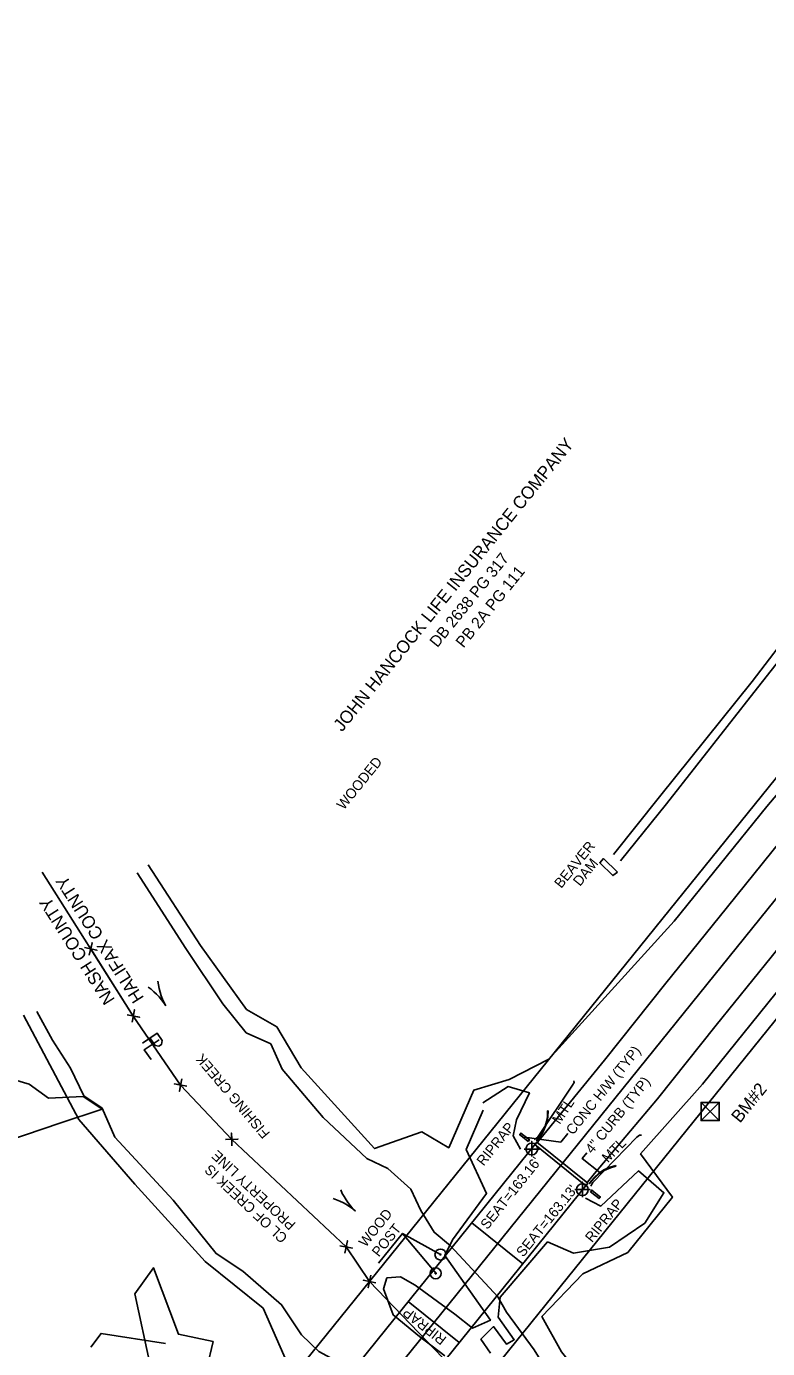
# Model space of a CAD drawing. Extents: x 2292498 to 2294521, y 891760 to 894087.
# Drawn here: x 2293733 to 2294026, y 893552 to 894075 of the extents above; entities that cross this region are included whole.
import ezdxf

# ---------------------------------------------------------------- set-up
doc = ezdxf.new("R2010")
doc.units = 0
for name, color, linetype in [('CTL Vertical Benchmark CELL', 7, 'Continuous'), ('CTL Vertical Benchmark Text', 7, 'Continuous'), ('Exist Boundary County Line', 7, 'Continuous'), ('Exist Boundary County Line Text', 7, 'Continuous'), ('Exist Environmental Wetland Boundary', 7, 'Continuous'), ('Exist Environmental Wetland Boundary Leader', 7, 'Continuous'), ('Exist Guardrail', 7, 'Continuous'), ('Exist Guardrail Text', 7, 'Continuous'), ('Exist Horizontal Alignment', 7, 'Continuous'), ('Exist Hydro Jurisdictional Stream or Body of Water', 7, 'Continuous'), ('Exist Hydro Jurisdictional Stream or Body of Water Text', 7, 'Continuous'), ('Exist Hydro Stream Flow Arrow CELL', 7, 'Continuous'), ('Exist Hydro Stream or Body of Water', 7, 'Continuous'), ('Exist Other Culture Area Outline', 7, 'Continuous'), ('Exist Other Culture Area Outline Text', 7, 'Continuous'), ('Exist Other Culture Located Object CELL', 7, 'Continuous'), ('Exist Other Culture Located Object Leader', 7, 'Continuous'), ('Exist Other Culture Located Object Text', 7, 'Continuous'), ('Exist Property Corner CELL', 7, 'Continuous'), ('Exist Property Deed Book Text', 7, 'Continuous'), ('Exist Property Line', 7, 'Continuous'), ('Exist Property Line Text', 7, 'Continuous'), ('Exist Property Owner Text', 7, 'Continuous'), ('Exist Property PL Symbol CELL', 7, 'Continuous'), ('Exist Right of Way Line', 7, 'Continuous'), ('Exist Roads Curbs', 7, 'Continuous'), ('Exist Roads Curbs Leader', 7, 'Continuous'), ('Exist Roads Curbs Text', 7, 'Continuous'), ('Exist Roads EOP', 7, 'Continuous'), ('Exist Structure Major Bridge Seam', 7, 'Continuous'), ('Exist Structure Major Bridge Seat Cogo Point CELL', 7, 'Continuous'), ('Exist Structure Major Bridge Seat Top Elevation', 7, 'Continuous'), ('Exist Structure Major Bridge WW', 7, 'Continuous'), ('Exist Structure Major Bridge WW Leader', 7, 'Continuous'), ('Exist Structure Major Bridge WW Text', 7, 'Continuous'), ('Exist Structure Major Deck Tunnel Box Culvert', 7, 'Continuous'), ('Exist Vegetation Woods Line', 7, 'Continuous'), ('Exist Vegetation Woods Line Text', 7, 'Continuous')]:
    doc.layers.add(name, color=color, linetype=linetype)

msp = doc.modelspace()

# ---------------------------------------------------------------- linework, layer by layer
at = {"layer": 'CTL Vertical Benchmark CELL'}
msp.add_line((2294003.6, 893645.94), (2294003.6, 893645.94), dxfattribs=at)
msp.add_lwpolyline([(2294000, 893649.53), (2294007.18, 893649.53), (2294007.18, 893642.34), (2294000, 893642.34)], close=True, dxfattribs=at)
for points in [[(2294007.18, 893649.53), (2294000, 893642.34), (2294003.59, 893645.93), (2294007.18, 893642.34), (2294000, 893649.53)], [(2294003.59, 893645.93), (2294007.18, 893649.53), (2294000, 893649.53), (2294003.59, 893645.93)], [(2294003.59, 893645.93), (2294000, 893642.34), (2294007.18, 893642.34), (2294003.59, 893645.93)]]:
    msp.add_lwpolyline(points, dxfattribs=at)
at = {"layer": 'Exist Boundary County Line'}
msp.add_lwpolyline([(2294085.79, 893359.86), (2293944.67, 893485.57), (2293917.22, 893516.72), (2293910.74, 893535.04), (2293868.86, 893578.67), (2293859.65, 893592.34), (2293814.35, 893634.9), (2293794.17, 893656.4), (2293775.45, 893683.7), (2293739.35, 893740.54)], dxfattribs=at)
at = {"layer": 'Exist Environmental Wetland Boundary'}
for points in [[(2293763.13, 893646.9), (2293755.65, 893651.85), (2293741.86, 893651.22), (2293734.32, 893656.8), (2293714.14, 893662.61)], [(2293710.75, 893557.16), (2293717.8, 893589.35), (2293701.17, 893615.08), (2293712.47, 893629.8), (2293746.4, 893641.37), (2293763.13, 893646.9)]]:
    msp.add_lwpolyline(points, dxfattribs=at)
msp.add_lwpolyline([(2293806.99, 893554.95), (2293804.55, 893544.37), (2293782.24, 893545.05), (2293776.11, 893573.81), (2293783.44, 893584.11), (2293793.31, 893557.79)], close=True, dxfattribs=at)
at = {"layer": 'Exist Environmental Wetland Boundary Leader'}
msp.add_lwpolyline([(2293788.18, 893554.1), (2293762.68, 893558.12), (2293758.65, 893552.66)], dxfattribs=at)
at = {"layer": 'Exist Guardrail'}
for points in [[(2293934.04, 893634.81), (2293935.26, 893635.64), (2293949.18, 893656.3), (2293949.85, 893657.35), (2293949.68, 893658.04)], [(2293976.47, 893636.59), (2293975.69, 893636.57), (2293974.64, 893635.71), (2293957.21, 893617.78), (2293956.77, 893617.11), (2293956.36, 893616.38)]]:
    msp.add_lwpolyline(points, dxfattribs=at)
at = {"layer": 'Exist Horizontal Alignment'}
msp.add_line((2293668.45, 893282.57), (2294292.7, 894056.1), dxfattribs=at)
at = {"layer": 'Exist Hydro Jurisdictional Stream or Body of Water'}
for points in [[(2293876.14, 893623.32), (2293867.85, 893627.29), (2293850.52, 893643.52), (2293834.35, 893662.67), (2293829.82, 893672.66), (2293820.14, 893677.06), (2293810.8, 893688.53), (2293796.25, 893710.39), (2293777.03, 893740.29)], [(2293763.14, 893647.29), (2293755.83, 893652.18), (2293750.6, 893663.12), (2293743.5, 893674.18), (2293737.3, 893685.5)], [(2293841.91, 893557.56), (2293834.07, 893569.44), (2293818.72, 893582.82), (2293808.2, 893589.71), (2293791.2, 893610.86), (2293768.19, 893635.74), (2293763.14, 893647.29)], [(2293972.26, 893510.52), (2293957.43, 893525.98), (2293944.05, 893535.44), (2293934.04, 893551.57), (2293923.07, 893566.54), (2293919.68, 893572.56), (2293900.86, 893592.82), (2293894.49, 893598.15), (2293889.13, 893606.73), (2293885.23, 893615.23), (2293876.14, 893623.32)], [(2293922.02, 893454.77), (2293917.08, 893460.63), (2293906.04, 893474.31), (2293901.31, 893485.66), (2293890.38, 893498), (2293885.17, 893503.23), (2293885.42, 893510.43), (2293887.93, 893517.16), (2293886.05, 893521.05), (2293873.12, 893534.01), (2293866.59, 893539.82), (2293859.83, 893545.01), (2293848.78, 893550.96), (2293841.91, 893557.56)]]:
    msp.add_lwpolyline(points, dxfattribs=at)
at = {"layer": 'Exist Hydro Stream Flow Arrow CELL'}
for p, q in [((2293785.78, 893692), (2293785.78, 893692)), ((2293859.67, 893609.82), (2293859.67, 893609.82))]:
    msp.add_line(p, q, dxfattribs=at)
for points in [[(2293781.27, 893695.15), (2293782.46, 893694.3), (2293783.59, 893693.31), (2293784.68, 893692.31), (2293785.67, 893691.26), (2293786.61, 893690.12), (2293787.51, 893688.92), (2293788.32, 893687.7)], [(2293785.21, 893697.47), (2293785.37, 893696.01), (2293785.7, 893694.55), (2293786.04, 893693.11), (2293786.48, 893691.74), (2293787.02, 893690.36), (2293787.64, 893688.99), (2293788.32, 893687.7)], [(2293857.53, 893614.88), (2293858.11, 893613.53), (2293858.85, 893612.23), (2293859.6, 893610.95), (2293860.43, 893609.77), (2293861.35, 893608.61), (2293862.33, 893607.48), (2293863.36, 893606.44)], [(2293854.44, 893611.5), (2293855.83, 893611.04), (2293857.19, 893610.42), (2293858.53, 893609.79), (2293859.79, 893609.07), (2293861.02, 893608.26), (2293862.23, 893607.37), (2293863.36, 893606.44)]]:
    msp.add_lwpolyline(points, dxfattribs=at)
at = {"layer": 'Exist Hydro Stream or Body of Water'}
for points in [[(2293965.42, 893747.6), (2293983.52, 893770.46), (2294020.17, 893816.01), (2294037.74, 893838.96), (2294073.63, 893884.39), (2294095.2, 893911.15), (2294125.99, 893949.6), (2294148.73, 893977.27), (2294148.61, 893978.43), (2294147.33, 893979.83), (2294128.27, 893998.23), (2294100.51, 894022.9)], [(2293968.14, 893745.05), (2293986.28, 893767.63), (2294022.34, 893813.58), (2294040.46, 893836.56), (2294069.7, 893872.94), (2294098.71, 893908.94), (2294129.49, 893948.14), (2294150.33, 893973.58), (2294152.51, 893976.22), (2294152.08, 893979.35), (2294149.75, 893982.98), (2294131.07, 893999.21), (2294104.21, 894024.33)]]:
    msp.add_lwpolyline(points, dxfattribs=at)
at = {"layer": 'Exist Other Culture Area Outline'}
for points in [[(2293966.96, 893740.61), (2293961.48, 893746.01), (2293959.94, 893744.35), (2293965.14, 893739.26), (2293966.96, 893740.61)], [(2293913.73, 893649.35), (2293923.67, 893655.79), (2293932.11, 893653.29), (2293926.96, 893642.65), (2293925.73, 893636.34), (2293928.53, 893631.02)], [(2293898.65, 893549.29), (2293888.68, 893556.92), (2293878.25, 893565.42), (2293874.45, 893575.74), (2293875.73, 893580.06), (2293881.14, 893580.52), (2293886.91, 893577.23), (2293902.55, 893565.71), (2293909.58, 893560.24), (2293916.7, 893563.37), (2293898.6, 893588.98), (2293901.73, 893595.13), (2293915.17, 893613.5), (2293907.14, 893630.86), (2293913.77, 893646.48)], [(2293954.36, 893611.57), (2293960.42, 893608.48), (2293975.24, 893622.43), (2293985.31, 893613.8), (2293977.71, 893601.77), (2293963.83, 893592.29), (2293949.53, 893589.84), (2293939.27, 893594.36), (2293920.58, 893572.42), (2293919.78, 893564.62), (2293926.1, 893555.62), (2293923.01, 893553.94), (2293917.96, 893560.82), (2293912.96, 893555.9), (2293916.74, 893550.26)]]:
    msp.add_lwpolyline(points, dxfattribs=at)
at = {"layer": 'Exist Other Culture Located Object CELL'}
for centre, radius in [((2293896.94, 893589.33), 2.18), ((2293896.94, 893589.33), 0.24), ((2293895.05, 893581.92), 2.18), ((2293895.05, 893581.92), 0.24)]:
    msp.add_circle(centre, radius, dxfattribs=at)
at = {"layer": 'Exist Other Culture Located Object Leader'}
msp.add_line((2293896.94, 893589.33), (2293881.94, 893597.66), dxfattribs=at)
msp.add_lwpolyline([(2293895.24, 893581.77), (2293881.94, 893597.66), (2293872.48, 893585.97)], dxfattribs=at)
at = {"layer": 'Exist Property Corner CELL'}
for p, q in [((2293758.6, 893710.24), (2293758.6, 893710.24)), ((2293775.45, 893683.7), (2293775.45, 893683.7)), ((2293794.17, 893656.4), (2293794.17, 893656.4)), ((2293814.35, 893634.9), (2293814.35, 893634.9)), ((2293859.65, 893592.34), (2293859.65, 893592.34)), ((2293868.86, 893578.67), (2293868.86, 893578.67))]:
    msp.add_line(p, q, dxfattribs=at)
for points in [[(2293756.16, 893710.78), (2293761.04, 893709.69), (2293758.6, 893710.24), (2293759.14, 893712.68), (2293758.05, 893707.8)], [(2293773, 893684.16), (2293777.91, 893683.24), (2293775.45, 893683.7), (2293775.91, 893686.16), (2293774.99, 893681.25)], [(2293796.63, 893655.94), (2293791.71, 893656.86), (2293794.17, 893656.4), (2293793.71, 893653.94), (2293794.63, 893658.86)], [(2293811.85, 893634.82), (2293816.84, 893634.98), (2293814.35, 893634.9), (2293814.27, 893637.4), (2293814.42, 893632.4)], [(2293857.19, 893592.81), (2293862.1, 893591.86), (2293859.65, 893592.34), (2293860.12, 893594.79), (2293859.17, 893589.88)], [(2293871.31, 893578.2), (2293866.4, 893579.15), (2293868.86, 893578.67), (2293868.38, 893576.22), (2293869.33, 893581.13)]]:
    msp.add_lwpolyline(points, dxfattribs=at)
at = {"layer": 'Exist Property Line'}
for p, q in [((2293775.45, 893683.7), (2293758.6, 893710.24)), ((2293859.65, 893592.34), (2293814.35, 893634.9))]:
    msp.add_line(p, q, dxfattribs=at)
for points in [[(2293794.17, 893656.4), (2293775.45, 893683.7)], [(2293814.35, 893634.9), (2293794.17, 893656.4)], [(2293868.86, 893578.67), (2293859.65, 893592.34)]]:
    msp.add_lwpolyline(points, dxfattribs=at)
at = {"layer": 'Exist Property PL Symbol CELL'}
msp.add_line((2293782.43, 893673.52), (2293782.43, 893673.52), dxfattribs=at)
for points in [[(2293779.06, 893672.97), (2293784.86, 893676.95), (2293786.87, 893674.01), (2293786.56, 893672.38), (2293785.6, 893671.73), (2293784.04, 893672.06), (2293782.02, 893675)], [(2293785.61, 893674.32), (2293779.78, 893670.32), (2293782.45, 893666.43)]]:
    msp.add_lwpolyline(points, dxfattribs=at)
at = {"layer": 'Exist Right of Way Line'}
for p, q in [((2293645.1, 893301.41), (2294269.35, 894074.94)), ((2293691.79, 893263.73), (2294316.04, 894037.26))]:
    msp.add_line(p, q, dxfattribs=at)
at = {"layer": 'Exist Roads Curbs'}
for points in [[(2293939.29, 893646.19), (2293939.21, 893643.84), (2293938.91, 893641.94), (2293938.33, 893640.17), (2293937.23, 893637.76), (2293936.2, 893636.2), (2293934.87, 893634.4)], [(2293939.48, 893646.14), (2293939.4, 893643.82), (2293939.1, 893641.89), (2293938.5, 893640.1), (2293937.39, 893637.67), (2293936.35, 893636.09), (2293935.02, 893634.29), (2293934.87, 893634.4)], [(2293939.29, 893646.19), (2293939.48, 893646.14)], [(2293966.28, 893624.56), (2293964.02, 893623.84), (2293961.55, 893622.86), (2293959.58, 893621.55), (2293957.67, 893619.76), (2293955.71, 893617.52)], [(2293966.31, 893624.27), (2293964.12, 893623.57), (2293961.68, 893622.61), (2293959.75, 893621.33), (2293957.87, 893619.56), (2293955.92, 893617.33), (2293955.71, 893617.52)], [(2293966.31, 893624.27), (2293966.28, 893624.56)]]:
    msp.add_lwpolyline(points, dxfattribs=at)
at = {"layer": 'Exist Roads Curbs Leader'}
msp.add_lwpolyline([(2293960.02, 893621.85), (2293953.01, 893627.3), (2293954.84, 893629.56)], dxfattribs=at)
at = {"layer": 'Exist Roads EOP'}
for points in [[(2293935.28, 893633.81), (2293937.79, 893636.87), (2293961.83, 893666.23), (2293986.02, 893696.74), (2294007.23, 893722.82), (2294031.33, 893752.69), (2294058.41, 893786.02), (2294082.69, 893816.27), (2294107.66, 893847.21), (2294131.39, 893876.6), (2294158.26, 893909.62), (2294184.25, 893942.29), (2294211.73, 893976.1), (2294235.74, 894006.24), (2294255.79, 894031.21), (2294282.38, 894064.31)], [(2293955.11, 893617.9), (2293957.85, 893621.39), (2293982.73, 893650.99), (2294005.99, 893680.08), (2294027.69, 893706.97), (2294051.48, 893736.65), (2294078.15, 893769.54), (2294102.63, 893799.93), (2294128.01, 893831.31), (2294151.11, 893860.1), (2294178.02, 893893.21), (2294203.53, 893924.91), (2294231.5, 893959.53), (2294255.32, 893989.22), (2294275.52, 894013.95), (2294303.02, 894047.9)]]:
    msp.add_lwpolyline(points, dxfattribs=at)
at = {"layer": 'Exist Structure Major Bridge Seam'}
for p, q in [((2293934.29, 893632.85), (2293954.37, 893616.51)), ((2293909.32, 893601.88), (2293929.46, 893585.6)), ((2293884.2, 893570.82), (2293904.37, 893554.48))]:
    msp.add_line(p, q, dxfattribs=at)
at = {"layer": 'Exist Structure Major Bridge Seat Cogo Point CELL'}
for points in [[(2293930.06, 893631.08), (2293936.06, 893631.08), (2293933.06, 893631.08), (2293933.06, 893634.08), (2293933.06, 893628.08)], [(2293950.07, 893615), (2293956.07, 893615), (2293953.07, 893615), (2293953.07, 893618), (2293953.07, 893612)]]:
    msp.add_lwpolyline(points, dxfattribs=at)
for centre in [(2293933.06, 893631.08), (2293953.07, 893615)]:
    msp.add_circle(centre, 2.34, dxfattribs=at)
at = {"layer": 'Exist Structure Major Bridge WW'}
for points in [[(2293931.59, 893634.11), (2293929.35, 893635.89), (2293928.23, 893636.79), (2293928.71, 893637.41), (2293929.89, 893636.49), (2293932.1, 893634.73), (2293931.59, 893634.11)], [(2293956.28, 893614.2), (2293958.55, 893612.43), (2293959.64, 893611.48), (2293960.18, 893612.07), (2293959.04, 893613.02), (2293956.78, 893614.82), (2293956.28, 893614.2)]]:
    msp.add_lwpolyline(points, dxfattribs=at)
at = {"layer": 'Exist Structure Major Bridge WW Leader'}
msp.add_lwpolyline([(2293930.13, 893635.71), (2293944.53, 893633.79), (2293947.35, 893637.28)], dxfattribs=at)
at = {"layer": 'Exist Structure Major Deck Tunnel Box Culvert'}
msp.add_lwpolyline([(2293955.25, 893617.63), (2293935.05, 893633.81), (2293808.22, 893476.45), (2293828.45, 893460.21), (2293955.25, 893617.63)], dxfattribs=at)
at = {"layer": 'Exist Vegetation Woods Line'}
for points in [[(2294275.43, 894075.18), (2294226.51, 894014.61), (2294183.35, 893961.16), (2294158.03, 893929.81), (2294068.65, 893816.83), (2294026.01, 893766.63), (2293989.31, 893721.19), (2293939.84, 893666.63), (2293924.14, 893658.56), (2293910.07, 893654.4), (2293900.21, 893631.61), (2293889.51, 893637.85), (2293870.86, 893631.28), (2293841.9, 893663.23), (2293832.19, 893679.37), (2293820.24, 893686.32), (2293801.97, 893711.56), (2293781.32, 893743.5)], [(2294054.09, 893434.89), (2294014.85, 893475.1), (2293994.42, 893496.91), (2293989.72, 893508.14), (2293970.8, 893518.83), (2293959.99, 893531.71), (2293944.74, 893550.81), (2293937.07, 893564.86), (2293953.29, 893581.7), (2293971.02, 893590.11), (2293988.69, 893612), (2293976.08, 893629.18), (2294000.58, 893656.8), (2294032.96, 893696.89), (2294066.89, 893733.51), (2294113.65, 893791.41), (2294145.47, 893830.82), (2294186.13, 893872.69), (2294234.1, 893935.06), (2294280.63, 893992.69), (2294320.98, 894042.65)], [(2293732.08, 893683.99), (2293753.84, 893642.7), (2293776.04, 893617.13), (2293803.85, 893586.64), (2293826.81, 893568.1), (2293837.34, 893544.18), (2293818.76, 893515.97), (2293791.39, 893504.81), (2293772.49, 893487.57), (2293783.27, 893472.6), (2293705.95, 893376.86), (2293643.52, 893299.56), (2293587.64, 893230.36), (2293564.82, 893200.7)]]:
    msp.add_lwpolyline(points, dxfattribs=at)

# ---------------------------------------------------------------- texts
at = {"layer": 'CTL Vertical Benchmark Text'}
msp.add_text('BM#2       ', height=5, rotation=51.0765, dxfattribs=at).set_placement((2294015.39, 893641.08))
at = {"layer": 'Exist Boundary County Line Text'}
for s, p in [('HALIFAX COUNTY', (2293779.8, 893690.84)), ('NASH COUNTY', (2293768.36, 893690.2))]:
    msp.add_text(s, height=5, rotation=122.4237, dxfattribs=at).set_placement(p)
at = {"layer": 'Exist Guardrail Text'}
for rotation, p in [(56.0235, (2293944.1, 893640.61)), (45.7986, (2293963.21, 893625.43))]:
    msp.add_text('MTL', height=4, rotation=rotation, dxfattribs=at).set_placement(p)
at = {"layer": 'Exist Hydro Jurisdictional Stream or Body of Water Text'}
msp.add_text('FISHING CREEK', height=4, rotation=130.1887, dxfattribs=at).set_placement((2293829.75, 893637.35))
at = {"layer": 'Exist Other Culture Area Outline Text'}
for s, rotation, p in [('BEAVER', 51.0765, (2293944.71, 893733.94)), ('DAM', 51.0765, (2293952.12, 893734.76)), ('RIPRAP', 51.0765, (2293913.99, 893624.1)), ('RIPRAP', 51.0765, (2293956.89, 893593.82)), ('RIPRAP', 141.4727, (2293899.67, 893556.36))]:
    msp.add_text(s, height=4, rotation=rotation, dxfattribs=at).set_placement(p)
at = {"layer": 'Exist Other Culture Located Object Text'}
for s, p in [('WOOD', (2293867.35, 893591.97)), ('POST', (2293872.57, 893588.09))]:
    msp.add_text(s, height=4, rotation=51.0765, dxfattribs=at).set_placement(p)
at = {"layer": 'Exist Property Deed Book Text'}
for s, p in [('DB 2638 PG 317', (2293895.72, 893829.21)), ('PB 2A PG 111', (2293906.04, 893829.03))]:
    msp.add_text(s, height=4.5, rotation=51.0765, dxfattribs=at).set_placement(p)
at = {"layer": 'Exist Property Line Text'}
for s, p in [('PROPERTY LINE', (2293839.99, 893601.58)), ('CL OF CREEK IS ', (2293836.76, 893596.38))]:
    msp.add_text(s, height=4, rotation=136.7833, dxfattribs=at).set_placement(p)
at = {"layer": 'Exist Property Owner Text'}
msp.add_text('JOHN HANCOCK LIFE INSURANCE COMPANY', height=5, rotation=51.0765, dxfattribs=at).set_placement((2293858.02, 893795.89))
at = {"layer": 'Exist Roads Curbs Text'}
msp.add_text('4" CURB (TYP)', height=4, rotation=51.0765, dxfattribs=at).set_placement((2293956.95, 893628.92))
at = {"layer": 'Exist Structure Major Bridge Seat Top Elevation'}
for s, rotation, p in [("SEAT=163.16'", 51.3989, (2293915.51, 893598.96)), ("SEAT=163.13'", 50.9482, (2293929.64, 893588.05))]:
    msp.add_text(s, height=4, rotation=rotation, dxfattribs=at).set_placement(p)
at = {"layer": 'Exist Structure Major Bridge WW Text'}
msp.add_text('CONC H/W (TYP)', height=4, rotation=51.0765, dxfattribs=at).set_placement((2293949.32, 893636.35))
at = {"layer": 'Exist Vegetation Woods Line Text'}
msp.add_text('WOODED', height=4, rotation=51.0765, dxfattribs=at).set_placement((2293858.68, 893764.99))

doc.saveas('drawing.dxf')
